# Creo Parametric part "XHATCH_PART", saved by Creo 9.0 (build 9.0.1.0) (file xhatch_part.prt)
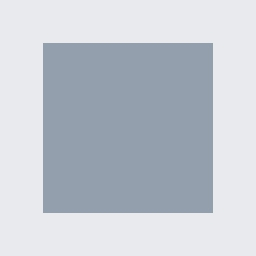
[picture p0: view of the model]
Units: Inch lbm Second (Pro/E Default); INCH, POUND, SECS

Created from: INLBS_PART_SOLID.PRT

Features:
  1. datum plane "RIGHT"
  2. datum plane "TOP"
  3. datum plane "FRONT"
  4. coordinate system
  5. extrusion "Extrude 1"

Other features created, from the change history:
  planar section "XSEC0001" (2 times)
  planar section "XSEC0002"

Surfaces: 6 plane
